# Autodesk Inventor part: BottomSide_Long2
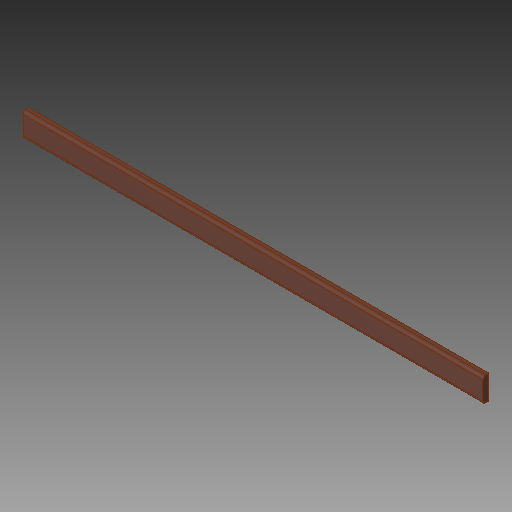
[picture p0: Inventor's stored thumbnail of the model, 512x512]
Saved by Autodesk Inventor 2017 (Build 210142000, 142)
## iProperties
Created: 2017-05
Part Number: BottomSide_Long2
Material: Generic
Document SubType Name: Modeling
Designer: Savy
Density: 1 g/cm^3
Appearance: Default
Author: Savy
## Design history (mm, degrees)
feature "SOLID1"
body "Solid1"
